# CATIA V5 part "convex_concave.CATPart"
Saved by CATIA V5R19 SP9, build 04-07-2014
Part number: Part38
Bounding box of the stored display mesh (mm): x -1 to 1, y -7.282 to 36.698, z -20.661 to 9.877
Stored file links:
  C:\Users\dolezab\Desktop\convex_concave.CATPart
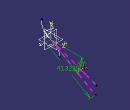
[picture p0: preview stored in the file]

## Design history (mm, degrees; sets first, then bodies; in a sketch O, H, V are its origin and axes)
Parameters
  alfa_c = 11 deg
  alfa = 0 deg
  r_kh = 9 mm
  r_kd = 9 mm
  d = 73.2 mm {= m_n *z}
  m_n = 4.575 mm
  z = 16
  da = 82.35 mm {= d+m_n *2}
  df = 61.7625 mm {= d -1.25*2*m_n}
  phi(r) = 4.4469 deg {= phi_real *180deg/PI}
  alfa_c_rad = 0.191986 {= alfa_c *PI/180deg}
  phi_real = 0.0776122
  x_real = 0.000274387
  y_real = 0.0390532
  alfa_steps = 0.349066 {= 20*PI/180}
  Real = 0.987688 {= cos(alfa_steps -alfa_c_rad )}
AxisSystem1: origin (0, 0, 0), X (1, 0, 0), Y (0, 1, 0), Z (0, 0, 1)
Set1
  Line1: type Angle, RefPoint vertex [YZ plane of AxisSystem1 | ZX plane of AxisSystem1 | XY plane of AxisSystem1], Curve edge [YZ plane of AxisSystem1 | XY plane of AxisSystem1], Support yz-plane, Start 0, End 39.0532, Angle -20
  Line2: type Angle, RefPoint vertex [YZ plane of AxisSystem1 | ZX plane of AxisSystem1 | XY plane of AxisSystem1], Curve edge [YZ plane of AxisSystem1 | XY plane of AxisSystem1], Support yz-plane, Start 0, End 41.3225, Angle -30
Body1 (main body)
  Sketch1 on YZ plane of AxisSystem1, origin (0, 0, 0), H (0, 1, 0), V (0, 0, 1)
    construction line L1 (-17.9, 3.4794) -> (15.1151, -2.9381)
    construction line L2 (2.7931, 14.3693) -> (-1.9874, -10.2245)
    arc A1 centre (1.7173, 8.8346) radius 9 from (-7.2222, 9.8766) to (0, 0) ccw
    arc A2 centre (-1.7173, -8.8346) radius 9 from (0, 0) to (7.2505, -8.0732) cw
    point P7 (-1.7173, -8.8346)
    line L3 (0, 0) -> (-2.646, 0.9631)
    point P9 (0, 0)
    point P10 (-2.646, 0.9631)
    line L4 (0, 0) -> (-5.0751, 2.9301)
    point P11 (0, 0)
    point P12 (-5.0751, 2.9301)
    line L5 (1.7173, 8.8346) -> (-2.646, 0.9631)
    line L6 (1.7173, 8.8346) -> (-5.0751, 2.9301)
    point P13 (-5.0751, 2.9301)
    construction circle A3 centre (0, 36.6) radius 36.6
    point P14 (0, 36.6)
    construction line L7 (0, 36.6) -> (-2.646, 0.9631)
    construction line L8 (0, 0) -> (2.646, -0.9631)
    point P15 (2.646, -0.9631)
    construction line L9 (2.646, -0.9631) -> (0, 36.6)
    point P16 (2.646, -0.9631)
    angle H L1 = 11
    radius A1 = 9
    radius A2 = 9
    angle L3 H = 20
    distance P10 V = 2.646 (reference)
    angle L4 H = 30
    distance V P12 = 5.0751 (reference)
    angle L5 L2 = 18 (reference)
    angle L6 L2 = 38 (reference)
    angle L2 V = 11 (reference)
    radius A3 = 36.6 {= d /2}
    angle L7 V = 4.2464 (reference)
    angle L8 H = 20
    angle L9 V = 4.0294 (reference)
    coincidence: L1 O, L2 O, P7 L2, P9 A1, P9 L1, P10 A1, P12 A1, P11 O, P13 L4, P13 A1, A3 P9, P14 V, P15 A2, P16 A2, P16 P15
    perpendicularity: L1 L2
    tangency: A2 A1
